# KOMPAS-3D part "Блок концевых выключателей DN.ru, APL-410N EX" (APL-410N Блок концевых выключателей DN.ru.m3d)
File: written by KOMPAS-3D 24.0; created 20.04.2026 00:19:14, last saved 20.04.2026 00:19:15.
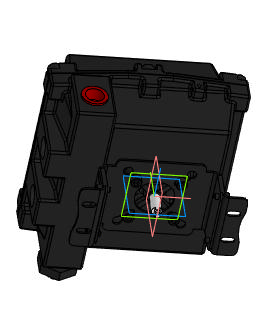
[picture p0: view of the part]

Document properties: Автор: R2D2; Полное имя файла: E:\Работа\Зайцев\Аксессуары для пневмоприводов\Блок концевых выключателей DN.ru\APL-410N EX Блок концевых выключателей DN.ru\APL-410N Блок концевых выключателей DN.ru.m3d

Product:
- Part/product: Блок концевых выключателей DN.ru  | designation APL-410N EX
    Масса: 1.1
    Раздел спецификации: Прочие изделия
    Примечание: D290-00324

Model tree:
1. Операция без истории:1

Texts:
  APL-410N EX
